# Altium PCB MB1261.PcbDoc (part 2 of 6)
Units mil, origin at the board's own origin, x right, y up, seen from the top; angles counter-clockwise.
Board outline 5119.1 x 2638.79 mil, 6 copper layers (TOP, L2_GND, L3_SIG, L4_VCC, L5_GND, BOTTOM), stack 61 mil thick; 336 components, 316 nets, 1358 pads, 871 vias.
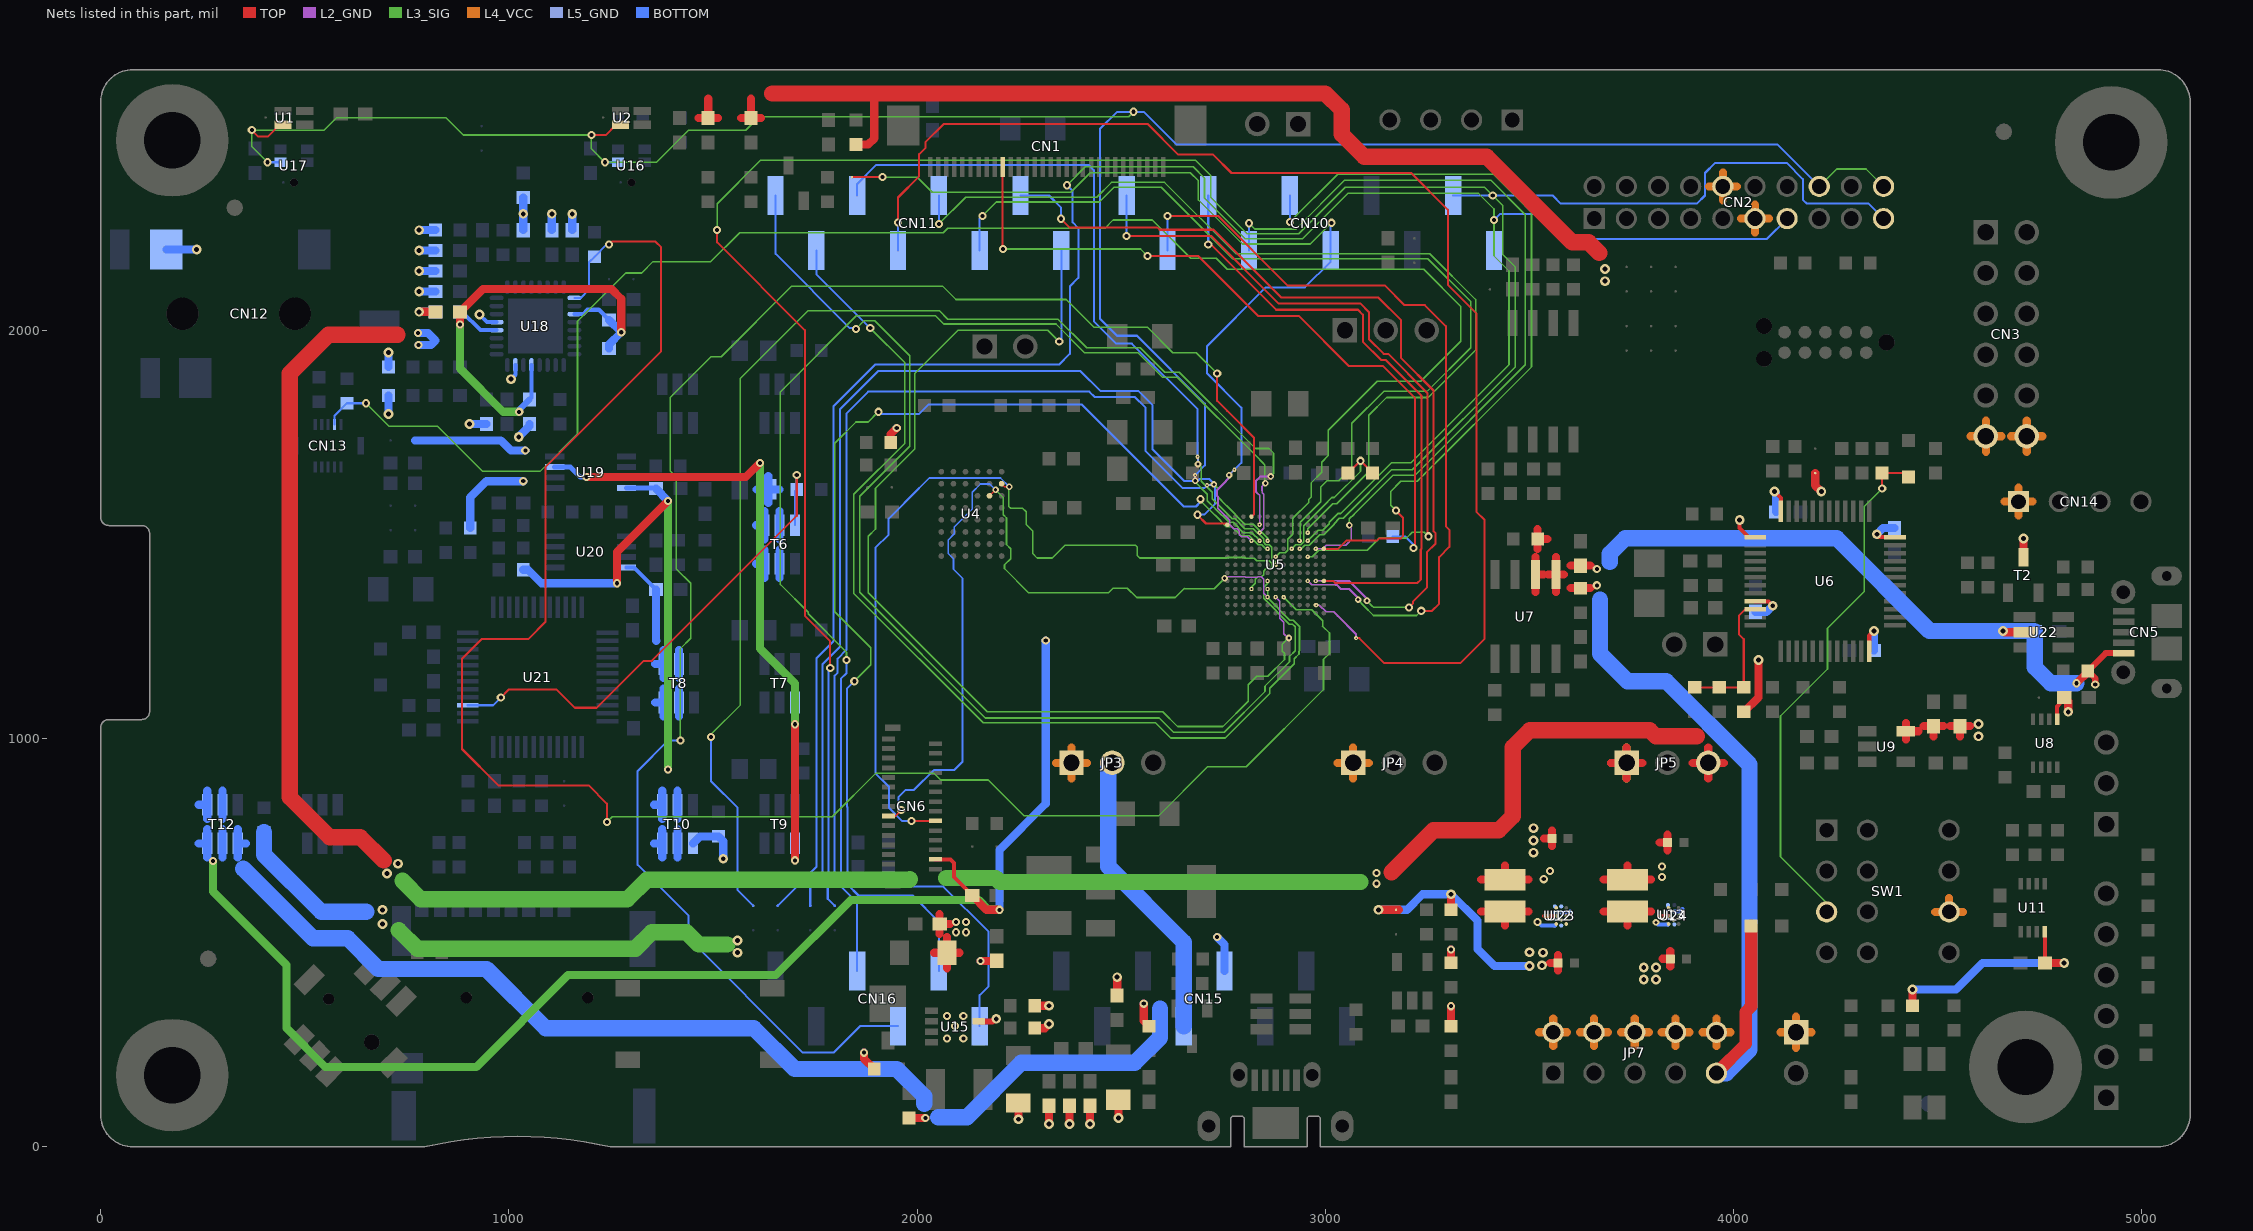
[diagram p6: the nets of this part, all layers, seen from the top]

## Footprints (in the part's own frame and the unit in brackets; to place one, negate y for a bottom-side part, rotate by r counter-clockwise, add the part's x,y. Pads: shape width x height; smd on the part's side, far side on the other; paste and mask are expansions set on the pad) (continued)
SOT23-5 [mil] "SOT23-5"
  rect 25x45 smd: 1(-37.4,-47.24) 2(0,-47.24) 3(37.4,-47.24) 4(37.4,47.24) 5(-37.4,47.24)
  silkscreen extent -65,-101 65,35, body extent -57,-70 57,70, height 150
SOT23-6L [mil] "SOT23-6L"
  rect 25x53 smd: 1(-37.4,-47.24) 2(0,-47.24) 3(37.4,-47.24) 4(37.4,47.24) 5(0,47.24) 6(-37.4,47.24)
  silkscreen extent -75,-95 65,85, body extent -57,-75 57,75, height 150
SOT-23 [mil] "SOT-23"
  rect 25x45 smd: 1(-37.4,-43.31) 2(37.4,-43.31) 3(0,43.31)
  silkscreen extent -60,-35 60,35, body extent -60,-70 60,70, height 150
SOT-223 [mil] "SOT-223"
  rect 71x40 smd: 1(124.02,-90.55) 2(124.02,0) 3(124.02,90.55)
  rect 71x130 smd: 4(-124.02,0)
  silkscreen extent -75,-147 192,130, body extent -160,-128 160,128, height 150
SQT-110-01-F-D-RA [mil] "SQT-110-01-F-D-RA"
  rect 52x52 hole 36: 1(359.27,175)
  round 52 hole 36: 2(280.53,175) 3(201.79,175) 4(123.05,175) 5(44.31,175) 6(-34.43,175) 7(-113.17,175) 8(-191.91,175) 9(-270.65,175) 10(-349.39,175) 11(359.27,96.26) 12(280.53,96.26) 13(201.79,96.26) 14(123.05,96.26) 15(44.31,96.26) 16(-34.43,96.26) 17(-113.17,96.26) 18(-191.91,96.26) 19(-270.65,96.26) 20(-349.39,96.26)
  silkscreen extent -395,-204 405,186, body extent -402,-205 402,205, height 150
SSW-106-02-F-D-RA [mil] "SSW-106-02-F-D-RA"
  rect 60x60 / inner round 60 / far side rect 60x60 hole 40: 1(250,229.5)
  round 60 hole 40: 2(150,229.5) 3(50,229.5) 4(-50,229.5) 5(-150,229.5) 6(-250,229.5) 7(250,129.5) 8(150,129.5) 9(50,129.5) 10(-50,129.5) 11(-150,129.5) 12(-250,129.5)
  silkscreen extent -310,-266 320,243, body extent -310,-264 310,264, height 150
SSW-106-22-X-S-VS [mil] "SSW-106-22-X-S-VS"
  rect 40x95 smd: 1(250,67.5) 2(150,-67.5) 3(50,67.5) 4(-50,-67.5) 5(-150,67.5) 6(-250,-67.5)
  silkscreen extent -310,-47 310,149, body extent -310,-120 310,120, height 150
SSW-108-22-X-S-VS [mil] "SSW-108-22-X-S-VS"
  rect 40x95 smd: 1(350,67.5) 2(250,-67.5) 3(150,67.5) 4(50,-67.5) 5(-50,67.5) 6(-150,-67.5) 7(-250,67.5) 8(-350,-67.5)
  silkscreen extent -410,-47 414,152, body extent -410,-120 410,120, height 150
SSW-110-22-X-S-VS [mil] "SSW-110-22-X-S-VS"
  rect 40x95 smd: 1(450,67.5) 2(350,-67.5) 3(250,67.5) 4(150,-67.5) 5(50,67.5) 6(-50,-67.5) 7(-150,67.5) 8(-250,-67.5) 9(-350,67.5) 10(-450,-67.5)
  silkscreen extent -510,-47 510,153, body extent -510,-120 510,120, height 150
SW1_11R7X9R7-12R2X9R65-HDR_CPT [mil] "SW1_11R7X9R7-12R2X9R65-HDR_CPT"
  rect 52x52 hole 36: 1(-150,-150)
  round 52 hole 36: 2(-50,-150) 3(50,-150) 4(150,-150) 5(150,150) 6(50,150) 7(-50,150) 8(-150,150) " "(-150,-50) " "(-50,-50) " "(50,-50) " "(150,-50)
  TOP region: 24.02,-51.97 75.98,-51.97 75.98,151.97 24.02,151.97 24.02,-51.97
  TOP region: -75.98,-51.97 -24.02,-51.97 -24.02,151.97 -75.98,151.97 -75.98,-51.97
  TOP region: -175.98,-51.97 -124.02,-51.97 -124.02,151.97 -175.98,151.97 -175.98,-51.97
  TOP region: 124.02,-51.97 175.98,-51.97 175.98,151.97 124.02,151.97 124.02,-51.97
  silkscreen extent -240,-231 240,191, body extent -240,-191 240,191, height 150
TAN-A [mil] "TAN-A"
  rect 50x60 smd: 1(55,0) 2(-55,0)
  silkscreen extent -95,-45 105,45
TAN-B [mil] "TAN-B"
  rect 59x110 smd: 1(-67.5,0) 2(67.5,0)
  silkscreen extent -130,-65 110,65, body extent -100,-55 100,55, height 150
TC2050-IDC-NL [mil] "TC2050-IDC-NL"
  round 31 smd paste-50: 1(-100.2,-25) 2(-50.2,-25) 3(-0.2,-25) 4(49.8,-25) 5(99.8,-25) 6(99.8,25) 7(49.8,25) 8(-0.2,25) 9(-50.2,25) 10(-100.2,25)
  round 39 hole 39 unplated: " "(-150.2,0) " "(149.8,-39.96) " "(149.8,39.96)
  TOP pour cut-out: -100.2,18.9 -100.2,-14.9 99.8,-14.9 99.8,18.9 -100.2,18.9
  Multi-Layer pour cut-out: -150.2,-35.43 -163.76,-32.73 -175.25,-25.05 -182.93,-13.56 -185.63,0 -185.63,0 -182.93,13.56 -175.25,25.05 -163.76,32.73 -150.2,35.43 -150.2,35.43 -136.64,32.73 -125.15,25.05 -117.47,13.56 -114.77,0 -114.77,0 -117.47,-13.56 -125.15,-25.05 -136.64,-32.73 -150.2,-35.43
  Multi-Layer pour cut-out: 149.8,4.53 136.24,7.23 124.75,14.91 117.07,26.4 114.37,39.96 114.37,39.96 117.07,53.52 124.75,65.01 136.24,72.69 149.8,75.39 149.8,75.39 163.36,72.69 174.85,65.01 182.53,53.52 185.23,39.96 185.23,39.96 182.53,26.4 174.85,14.91 163.36,7.23 149.8,4.53
  Multi-Layer pour cut-out: 149.8,-75.39 136.24,-72.69 124.75,-65.01 117.07,-53.52 114.37,-39.96 114.37,-39.96 117.07,-26.4 124.75,-14.91 136.24,-7.23 149.8,-4.53 149.8,-4.53 163.36,-7.23 174.85,-14.91 182.53,-26.4 185.23,-39.96 185.23,-39.96 182.53,-53.52 174.85,-65.01 163.36,-72.69 149.8,-75.39
  silkscreen extent -245,-132 245,133, body extent -245,-133 245,133, height 150
USOP8_0R5_2X3R1 [mil] "USOP8_0R5_2X3R1"
  rect 11x28 smd mask+2: 1(-29.53,-59.06) 2(-9.84,-59.06) 3(9.84,-59.06) 4(29.53,-59.06) 5(29.53,59.06) 6(9.84,59.06) 7(-9.84,59.06) 8(-29.53,59.06)
  silkscreen extent -47,-106 40,30, body extent -40,-75 40,75, height 150
XTAL_2SM_3R2X1R5 [mil] "XTAL_2SM_3R2X1R5"
  rect 51x63 smd: 1(-45.78,-1) 2(44.78,-1)
  silkscreen extent -86,-46 84,44, body extent -72,-31 72,31, height 150
XTAL_2SM_3R2X2R5 [mil] "XTAL_2SM_3R2X2R5"
  rect 67x75 smd: 1(-49.21,0) 2(49.21,0)
  silkscreen extent -63,-49 63,49, body extent -85,-50 85,50, height 150

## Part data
B1: library part "SW PUSHBUTTON", "SE Push Button TD-0341 [RESET/Black]", Manuf_1=Chau-hua, Manuf_2=wealthmetal, Manuf_Part_1=CTSM-644N-V-T/R
B2: library part MT-008A, "Joystick", Manuf_1=XIEJIA
C1 C2 C4 C5 C7 C10 C12 C14 C15 C16 C17 C18 C21 C22 C24 C25 C26 C27 C28 C29 C30 C31 C33 C34 C44 C46 C51 C58 C59 C60 C66 C71 C72 C73 C80 C81 C82 C83 C85 C86 C87 C88 C89 C90 C92 C93 C94 C95 C96 C97 C98 C101 C102 C103 C104 C105: library part Cap, "Capacitor,100nF,10%,16V,X7R,0603,YAGEO", Manuf_1=YAGEO
C3 C62 C63 C99: library part Cap, "Capacitor,100nF,10%,16V,X7R,0603,YAGEO", Manuf_1=YAGEO, Manuf_Part_1=CC0603KRX7R7BB104
C6: library part "Cap Pol1", "TAN Capacitor,4.7uF,10%,16V,A Type,AVX", Manuf_1=AVX
C8 C13 C91 C100: library part "Cap Pol1", "Tan Capacitor,1uF,10%,16V,Tan-A,TAJA105K016R", Manuf_1=AVX
C9 C11: library part Cap, "Capacitor,5.6pF,0.25P,50V,NPO,0603", Manuf_1=YAGEO
C19 C32 C35 C67 C69 C70 C74 C77 C78 C79 C84: library part Cap, "Capacitor,1uF,0603,16V,10%,X5R,YAGEO", Manuf_1=YAGEO
C20 C23: library part Cap, "Capacitor,10pF,5%,50V,NPO,0603,YAGEO", Manuf_1=YAGEO
C36 C47 C57: library part MCD-00017, "Capacitor, MLCC, 10nF, 50V, X7R, +/-10%, 0603, T=0.8mm", Manufacturer=YAGEO, Package=0603
C37 C55 C61: library part "Cap Pol1", "TAN Capacitor,10uF,10%,16V,A Type,AVX", Manuf_1=AVX
C40 C41 C42 C43: library part MCD-01532, "Capacitor, MLCC, 10uF, 10V, X5R, +/-20%, 0402, T=0.5mm", Manufacturer=MURATA, Manufacturer_Part_Number=GRM155R61A106ME11, Package=0402
C45: library part "Cap Pol1", "Tan Capacitor,10uF,10%,25V,Tan-B,TAJB106K025RNJ", Manuf_1=AVX
C48: library part CAP, "Capacitor,4.7uF,50V,X7R,10%,1206", Manuf_1=YAGEO
C54: library part Cap, "Capacitor,4.7uF,16V, X5R,10%,0603", Manuf_1=YAGEO
C56: library part "Cap Pol1", "Capacitor,4.7uF,±10%,X7R,10V,1206,C1206X475K8NAC", Manuf_1=Kemet
C64 C65: library part Cap, "Capacitor,150pF,0603,50V,5%,NPO", Manuf_1=YAGEO
C68: library part Cap, "Capacitor,10uF,10%,10V,X5R,0603,C1608X5R1A106K080AC", Manuf_1=TDK, Manuf_Part_1=C1608X5R1A106KT000E
C75 C76: library part Cap, "Capacitor,22nF,10%,25V,X7R,0603", Manuf_1=YAGEO
CN1: "TOWNES -  Connector FFC/FPC ZIF 0.5mm 30 pins, Lower Contacts", Manuf_1=TOWNES, Manuf_Part_2=TFP-A330ZH-BT1-ECX
CN2: library part "Header 10X2A", "Header, 10-Pin, Dual row", Manuf_1=ATOM, Manuf_Part_1=FH200210C-12000
CN3: library part "Header 6X2A", "Header, 6-Pin, Dual row", Manuf_1=ATOM, Manuf_Part_1=FH254206C-1600
CN4: "Footprint for TC2050-IDC-430 plug of nails (TM) cable for MP430", Manuf_1=None
CN5 CN8: Manuf_1=MOLEX
CN6: library part FH26-29S-0.3SHW, "29pins FPC connector", Manuf_1=Hirose
CN7: library part "Header 6", "Header, 6-Pin", Manuf_1=lyconn
CN9 CN14: library part "Header 4", "Header, 4-Pin"
CN10: library part MCD-00301, "Socket, 10x1, 2.54mm, VR, SMD, T=9.78mm", Manufacturer=SAMTEC, Manufacturer_Part_Number=SSW-110-22-L-S-VS
CN11 CN15: library part "Header 8X1_Female", "Header, 8-Pin, Single row,female", Manuf_1=SAMTEC
CN12: Manuf_1=QIAOD
CN13: library part "Header 5X2A", "Header, 5-Pin, Dual row", Manuf_1=Hirose
CN16: library part MCD-00299, "Socket, 6x1, 2.54mm, VR, SMD, T=9.78mm", Manufacturer=SAMTEC, Manufacturer_Part_Number=SSW-106-22-L-S-VS
CN17: library part SMS016AFA5E, Manuf_1=Yamaichi
D1 D3 D6 U22: Manuf_1=STM
D2 D4: library part BAT60JFILM, "BAT60JFILM", Manuf_1=STM
D5: "4-line ESD protection", Manuf_1=STM, Manuf_Part_1=ESDA5V3L
JP1: library part JP2, "2 PIN Jumper", Manuf_1=lyconn, Manuf_Part_1=313102S111116
JP2: library part Jumper3, "Jumper 3 pins", Manuf_1=lyconn, Manuf_Part_1=313103S111116
JP3 JP5 JP6: library part Jumper3, Manuf_1=lyconn, Manuf_Part_1=313103S111116
JP4: Manuf_1=lyconn, Manuf_Part_1=313103S111116
JP7: library part "Header 5X2M", "Pin Header male,2.54mm,2*5,L=11.6,180,1U,DIP", Manuf_1=Lyconn
JP8 JP9 JP10: library part JP2, Manuf_1=lyconn, Manuf_Part_1=313102S111116
L1 L4 L5 L6 L8: library part MCD-00047, "Ferrite bead, 600R @1 00MHz, +/-25%, 350mA, 0R5, 0603, T=0.8mm", Manufacturer=TAI-TECH, Package=0603
L2 L3: library part Inductor, "Inductor", Manuf_1=TDK, Manuf_Part_1=VLS252010HBX-2R2M-1
L7: library part Inductor, "IND,4.7uH,1A,1210,LQH32PN4R7NN0L", Manuf_1=Murata
LD1: library part MCD-02785, "LED, Orange, 2V2, 5mA, 0603", Manufacturer=EVERLIGHT, Manufacturer_Part_Number=19-217/S2C-AM2N2VY/6T, Package=0603
LD2 LD3 LD6 LD8: library part MCD-02901, "LED, Green, 2V, 20mA, 0603", Manufacturer=EVERLIGHT, Manufacturer_Part_Number=19-217/G7C-AN1P2/6T, Package=0603
LD4 LD7: library part MCD-02787, "LED, Red, 1V7 To 2V2, 5mA, 0603", Manufacturer=EVERLIGHT, Manufacturer_Part_Number=19-217/R6C-AL1M2VY/6T, Package=0603
LD5: library part MCD-02402, "LED Bicolor, Red/Yellow-Green , 2V, 20mA, 4-PLCC", Manufacturer=EVERLIGHT, Manufacturer_Part_Number=67-22SURSYGC/S530-A2/TR8, Package=4-PLCC
R1: library part res1, "Resistor,680R,0603,1%,YAGEO", Manuf_1=YAGEO
R2 R112: library part res1, "Resistor,510R,0603,1%,YAGEO", Manuf_1=YAGEO
R4 R5 R16 R25 R35 R56 R59 R60 R63 R66 R69 R71 R102: library part res1, "Resistor, 100 ,0603,1%,YAGEO", Manuf_1=YAGEO
R6 R7 R8 R26 R28 R29 R100: library part res1, "Resistor, 22 ,0603,1%,YAGEO", Manuf_1=YAGEO
R12 R18 R130: library part res1, "Resistor, 0 ,0603,1%,YAGEO", Manuf_1=YAGEO, Manuf_Part_1=RC0603JR-070RL
R13 R14 R15 R17 R20 R33 R48 R52 R53 R54 R73 R76 R81 R84 R94 R106 R109 R110 R115 R116 R117: library part res1, "Resistor,100K,0603,1%,YAGEO", Manuf_1=YAGEO
R21 R31 R41 R77 R89 R99 R104: library part res1, "Resistor,100K,0603,1%,YAGEO", Manuf_1=YAGEO, Manuf_Part_1=RC0603FR-07100KL
R22 R45 R49: library part res1, "Resistor,4.7K,0603,1%,YAGEO", Manuf_1=YAGEO
R23: library part res1, "Resistor,2.7K,0603,1%,YAGEO", Manuf_1=YAGEO
R24: library part Res_0_5%_0402, "Resistor,0,0603,5%,YAGEO", Manuf_1=YAGEO, Manuf_Part_1=RC0603JR-070RL
R27 R30 R32 R44 R78 R83 R91 R113: library part res1, "Resistor,10K,0603,1%,YAGEO", Manuf_1=YAGEO
R34: library part res1, "Resistor,36K,0603,1%,YAGEO", Manuf_1=YAGEO
R36 R68: library part res1, "Resistor", Manuf_1=YAGEO, Manuf_Part_1=RC0603FR-07820RL
R37 R42 R43: library part res1, "Resistor,1.5K,0603,1%,YAGEO", Manuf_1=YAGEO
R46 R47 R51 R55 R57 R70 R80 R93 R105 R114 R129: library part res1, "Resistor, 0 ,0603,1%,YAGEO", Manuf_1=YAGEO
R50 R82: library part res1, "Resistor,2.2K,0603,1%,YAGEO", Manuf_1=YAGEO
R58 R62 R64: library part res1, "Resistor, 47K,0603,1%,YAGEO", Manuf_1=YAGEO
R65: library part res1, "Resistor, 10K,0603,1%,YAGEO", Manuf_1=YAGEO
R67: library part res1, "Resistor,10R,0603,1%,YAGEO", Manuf_1=YAGEO
R72: library part res1, "Resistor,1K,0603,1%", Manuf_1=YAGEO, Manuf_Part_1=RC0603FR-071KL
R74: library part res1, "Resistor, 330R , 0603,1%,YAGEO", Manuf_1=YAGEO
R75: library part res1, "Resistor, 620R , 0603,1%,YAGEO", Manuf_1=YAGEO
R79: library part res1, "Resistor,10K,0603,1%,YAGEO", Manuf_1=YAGEO, Manuf_Part_1=RC0603FR-0710KL
R85: library part Res_1_1%_0805, "Resistor,1,0805,1%,YAGEO", Manuf_1=YAGEO, Manuf_Part_1=RC0805FR-071RL
R86 R90: library part res1, "Resistor,50R,0603,1%,YAGEO", Manuf_1=YAGEO
R87 R88: library part res1, "Resistor,1.5K,0603,1%,YAGEO", Manuf_1=YAGEO, Manuf_Part_1=RC0603FR-071K5L
R92 R96: library part res1, "Resistor,6.04K,0603,1%,YAGEO", Manuf_1=YAGEO
R95: library part Res_10K_1%_0805, "Resistor,10K,0805,1%,YAGEO", Manuf_1=YAGEO, Manuf_Part_1=RC0805FR-0710KL
R97 R103: library part res1, "Resistor,300K,0603,1%,YAGEO", Manuf_1=YAGEO
R98: library part res1, "Resistor,11K,0603,1%,YAGEO", Manuf_1=YAGEO
R101: library part res1, "Resistor,357K,0603,1%,YAGEO", Manuf_1=YAGEO
R107: library part Res_24_1%_0805, "Resistor,24,0805,1%,YAGEO", Manuf_1=YAGEO, Manuf_Part_1=RC0805FR-0724RL
R111: library part Res_620_1%_0805, "Resistor,620,0805,1%,YAGEO", Manuf_1=YAGEO, Manuf_Part_1=RC0805FR-07620RL
R118 R119 R120 R121 R122: library part res1, "Resistor,47K,0603,1%,YAGEO", Manuf_1=YAGEO, Manuf_Part_1=RC0603FR-0747KL
R123: library part res1, "Resistor, 510R , 0603,1%,YAGEO", Manuf_1=YAGEO
R124: library part res1, "Resistor, 1M , 0603"
SB1 SB3 SB6 SB7 SB8 SB12 SB13 SB14 SB16 SB17 SB18 SB19 SB20 SB21 SB24 SB26 SB28: library part SB_ON, Manuf_1=YAGEO, Manuf_Part_1=RC0603JR-070RL
SB2 SB4 SB5 SB9 SB11 SB15 SB22 SB25 SB27: library part SB_OFF
SW1: "Gold Plated Contacts,4PST,1x4 Switch", Manuf_1="Grayhill Inc"
T1: library part 2N7000, Manuf_1=NXP
T2 T3: library part NPN, "NPN Bipolar Transistor", Manuf_Part_1=MMBT9013
T4 T5 T6 T7 T8 T9 T10 T11 T12: library part MCD-01926, "20 V, P-channel Trench MOSFET", Alternate_Manufacturer=N/A, Manufacturer=NEXPERIA, Package=TSOP6
U1 U2: library part MCD-01715, "MEMS audio sensor omnidirectional digital microphone for industrial applications", Manufacturer=STMICROELECTRONICS, Manufacturer_HQ_COO=EU, Package=HCLGA-4LD
U3: "Ultra Low Power 64M-BIT CMOS MXSMIO FLASH MEMORY", Manuf_1=MXIC
U4: "8M Bit static RAMs organized as 512K words by  16 bits.", Manuf_1=ISSI
U5: library part STM32L496G, Manuf_1=STM
U6: library part STM32F10x(48pin), "IC,STM32F103CBT6,LQFP-48", Manuf_1=STM
U7: Manuf_1=ST
U8 U11: Manuf_1=TI
U9: "Ultra low drop-low noise BiCMOS voltage, regulators low ESR capacitors compatible", Manuf_1=STM, Manuf_Part_2=LDK120DM33R
U10: library part LD1117S18TR, "Adjustable and fixed low drop positive voltage regulator", Manuf_1=STM
U12 U13: "High Efficiency Buck Converter", Manuf_1=TI
U14: "Enhanced single channel power switches", Manuf_1=ST
U15: library part STLD40DPMR, Manuf_1=ST
U16 U17: library part MCD-02122, "MEMS, Audio sensor Multi performance mode digital microphone", Manufacturer=STMICROELECTRONICS, Manufacturer_HQ_COO=EU, Manufacturer_Part_Number=MP23DB01HPTR, Package=RHLGA-5
U18: "Low-Power, Stereo Codec with Headphone Amp", Manuf_1=Cirrus
U19 U20: "Very high accuracy (5 礦) zero drift 5 V dual OpAmp", Manuf_1=STM
U21: library part MFX, "Multifunction expander", Manuf_1=STM
U23 U24: "400mA NanoQuiescent Step Down converter", Manuf_1=STM
X1: library part CRYSTAL_32K, "32.768kHz Crystal", Manuf_1=NDK, Manuf_Part_1=NX3215SA-32.768KHZ-EXS00A-MU00525
X2: library part XTAL_8M_NX3225GD, "Crystal 8Mhz, 8pF, -+50PPM, SMD", Manuf_1=NDK, Manuf_Part_1="NX3225GD 8MHz EXS00A-CG04874", Manuf_Part_2=NX3225GD-8.000M-STD-CRA-3
Z1: library part "D Schottky", "Schottky Diode", Manuf_1=STM

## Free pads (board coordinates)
  round 40 smd far side mask+40: 1(263.1,460) 1(4662.1,2486) ""(4478.1,105)
  round 40 smd mask+40: ""(263.1,460) ""(328.1,2300) ""(4662.1,2486)

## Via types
v1: diameter 20, hole 10, TOP to BOTTOM, tented both sides, 317 vias
v2: diameter 24, hole 12, TOP to BOTTOM, tented both sides, 289 vias
v3: diameter 10, hole 4, TOP to L2_GND, tented both sides, 76 vias
v4: diameter 10, hole 4, TOP to L3_SIG, tented both sides, 63 vias
v5: diameter 16, hole 8, L2_GND to L5_GND, tented both sides, 52 vias
v6: diameter 16, hole 8, TOP to BOTTOM, tented both sides, 43 vias
v7: diameter 10, hole 4, L5_GND to BOTTOM, tented both sides, 31 vias

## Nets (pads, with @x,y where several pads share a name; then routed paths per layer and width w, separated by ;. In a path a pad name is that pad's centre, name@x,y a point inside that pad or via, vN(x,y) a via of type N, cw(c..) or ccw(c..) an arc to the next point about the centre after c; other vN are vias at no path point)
1V8_CODEC: C5.1 C72.1 C73.1 C74.1 C77.1 SB19.2 U18.5 U18.12 U18.27 | length 1337.8
  TOP w20: v1(880,2014) C5.1@880,2045 936,2101 1251,2101 1275,2077 v1(1275,1995)
  L3_SIG w20: v1(880,2014) 880,1906 986,1800 v1(1025,1800)
  BOTTOM w10: C72.1@880,2045 885,2045 929.84,2000.16 U18.12@969.72,2000.16 ; C77.1@1050,1830 1055.16,1835.16 U18.5@1055.16,1914.72 ; U18.27@1160.28,2039.53 1182.4,2039.53 1192.87,2050 1220,2050 C73.1@1245,2025
  BOTTOM w15: v1(1025,1800) 1025,1805 C77.1@1050,1830
  BOTTOM w20: SB19.2@880,1975 v1(880,2014) C72.1@880,2045 ; C74.1@1245,1955 1245,1965 v1(1275,1995) C73.1@1245,2025
1V8_OUT: C41.1 JP5.3 L3.2 SB19.1 U13.C2 U24.E3 | length 5413.4
  TOP w20: 3681.98,654 L3.2@3740,654 ; 3740,688.52 L3.2@3740,654 ; 3798.02,654 L3.2@3740,654 ; 3819.08,745 C41.1@3838.1,745 ; 3838.1,725.98 C41.1@3838.1,745 ; 3838.1,764.02 C41.1@3838.1,745 ; 3900.08,940 JP5.3@3938.1,940 ; 3938.1,901.98 JP5.3@3938.1,940 ; 3938.1,978.02 JP5.3@3938.1,940 ; 3976.12,940 JP5.3@3938.1,940
  TOP w40: 693,701 636,758 561,758 463,856 463,1894 558,1989 727,1989 ; 3162,672 3265,775 3425,775 3459,809 3459,978 3501,1020 3795,1020 3810,1005 3910,1005
  L3_SIG w40: 739,651 784,606 1290,606 1338,654 1981,654 1982,655 ; 2071,658 2192,658 2202,648 3086,648
  BOTTOM w9: U13.C2@3854.87,575.87 3868.87,575.87 3875,582
  BOTTOM w20: v1(776.99,1992.99) 777,1992.93 802.07,1992.93 SB19.1@820,1975 809,1964 v1(778,1964)
  other v1: 3125,644 3825,660 3125,670 3825,686
  other v2: 701,669 728,693
1V8_SW: L3.1 U13.A1 U24.C3 | length 202.4
  TOP w9: 3820,565 U24.C3@3840.82,565
  TOP w20: 3681.98,576 L3.1@3740,576 ; 3740,541.48 L3.1@3740,576 ; 3798.02,576 L3.1@3740,576
  BOTTOM w10: v6(3810,549) 3814.62,544.38 U13.A1@3839.13,544.38
3V3_LCD: C44.1 CN6.26 R99.2 R130.2 SB20.1 T12.1 T12.2 T12.5 T12.6 | length 4246.6
  TOP w10: CN6.26@2044.44,703.41 2081.59,703.41 2090,695 2090,660 C44.1@2135,615
  TOP w20: R130.2@1935,1725 1935,1745 v1(1950,1760) ; C44.1@2135,615 2170,580 v1(2202,580)
  L3_SIG w20: v1(275,700) 275,625 455,445 455,290 550,195 920,195 1145,420 1653.49,420 1837.49,604 2151,604 2175,580 v1(2202,580)
  BOTTOM w20: 240.18,742.76 T12.6@260.7,742.76 ; 240.18,837.24 T12.1@260.7,837.24 ; 260.7,708.24 T12.6@260.7,742.76 ; 260.7,777.28 T12.6@260.7,742.76 ; 260.7,802.72 T12.1@260.7,837.24 ; 260.7,871.76 T12.1@260.7,837.24 ; 298.1,708.24 T12.5@298.1,742.76 298.1,777.28 ; 298.1,802.72 T12.2@298.1,837.24 298.1,871.76 ; SB20.1@770,1730 980,1730 1005,1705 v1(1040,1705) ; R99.2@905,1515 905,1590 945,1630 v1(1035,1630) ; v1(2202,580) 2202,727 2315,840 v1(2315,1240)
3V3_OUT: C40.1 CN3.6 CN3.12 CN15.4 JP4.1 JP5.1 L2.2 LD1.1 LD2.1 R64.1 R74.1 R75.1 R77.2 R123.1 T12.4 U12.C2 U23.E3 | length 6502.9
  TOP w20: 1464.08,2520 LD1.1@1488.1,2520 ; 1488.1,2567.1 LD1.1@1488.1,2520 ; 1512.12,2520 LD1.1@1488.1,2520 ; 1569.08,2520 LD2.1@1593.1,2520 ; 1593.1,2567.1 LD2.1@1593.1,2520 ; 1617.12,2520 LD2.1@1593.1,2520 ; R123.1@1850,2455 1880,2455 1895,2470 1895,2580 ; R77.2@1980,70 v1(2020,70) ; v1(2555,350) 2555,308.1 R74.1@2568.1,295 ; R75.1@3308.1,295 v1(3308.1,343.9) ; R64.1@3308.1,450 v1(3308.1,483.1) ; 3381.98,654 L2.2@3440,654 ; 3440,688.52 L2.2@3440,654 ; 3498.02,654 L2.2@3440,654 ; 3535.98,755 C40.1@3555,755 ; 3555,735.98 C40.1@3555,755 ; 3555,774.02 C40.1@3555,755 ; 3700.08,940 JP5.1@3738.1,940 ; 3738.1,901.98 JP5.1@3738.1,940 ; 3738.1,978.02 JP5.1@3738.1,940 ; 3776.12,940 JP5.1@3738.1,940
  TOP w40: 1645,2580 1895,2580 3000,2580 3040,2540 3040,2480 3095,2425 3395,2425 3605,2215 3645,2215 3671,2189
  L4_VCC w20: 3030.08,940 JP4.1@3068.1,940 ; 3068.1,901.98 JP4.1@3068.1,940 ; 3068.1,978.02 JP4.1@3068.1,940 ; 3106.12,940 JP4.1@3068.1,940 ; 3700.08,940 JP5.1@3738.1,940 ; 3738.1,901.98 JP5.1@3738.1,940 ; 3738.1,978.02 JP5.1@3738.1,940 ; 4580.08,1740 CN3.6@4618.1,1740 ; 4618.1,1701.98 CN3.6@4618.1,1740 ; 4618.1,1778.02 CN3.6@4618.1,1740 ; 4656.12,1740 CN3.6@4618.1,1740 ; 4680.08,1740 CN3.12@4718.1,1740 ; 4718.1,1701.98 CN3.12@4718.1,1740 ; 4718.1,1778.02 CN3.12@4718.1,1740 ; 4756.12,1740 CN3.12@4718.1,1740
  BOTTOM w9: U12.C2@3577.87,572.87 3595.87,572.87 3600,577
  BOTTOM w20: 335.5,708.24 T12.4@335.5,742.76 ; 335.5,777.28 T12.4@335.5,742.76 ; 356.02,742.76 T12.4@335.5,742.76 ; v1(2735,513) 2753.1,494.9 CN15.4@2753.1,430
  BOTTOM w40: 349,681 520,510 605,510 680,435 945,435 1090,290 1600,290 1700,190 1950,190 2017,123 2017,105 ; 2052,72 2122,72 2255,205 2533.1,205 2595,266.9 2595,338
  other v1: 3535,655 3550,675
  other v2: 3510,720 3510,750 3510,780 3685,2120 3685,2150
3V3_SW: L2.1 U12.A1 U23.C3 | length 227.1
  TOP w9: 3535,565 U23.C3@3565.82,565
  TOP w20: 3381.98,576 L2.1@3440,576 ; 3440,541.48 L2.1@3440,576 ; 3498.02,576 L2.1@3440,576
  BOTTOM w9: v1(3520,550) 3528.62,541.38 U12.A1@3562.13,541.38
5V_STL: D1.1 R24.2 SW1.3 | length 1293.9
  TOP w5: v1(4364.1,1611.9) R24.2@4364.1,1650 4419.81,1650 D1.1@4429.1,1640.71
  L3_SIG w4: SW1.3@4228.1,575 4228.1,596.9 4115,710 4115,1055 4230,1170 4230,1270 4320,1360 4320,1567.8 v1(4364.1,1611.9)
5V_USB_CHARGER: C19.2 C105.1 CN5.1 D3.1 JP7.9 R32.1 R36.2 R44.1 U7.1 U7.2 U22.5 | length 3826.6
  TOP w15: v1(4886,1132) 4886,1147.1 R44.1@4868.1,1165 4911.92,1208.82 CN5.1@4955.7,1208.82
  TOP w20: 3515,1358.38 U7.2@3515,1401.4 ; 3515,1444.42 U7.2@3515,1401.4 ; 3520,1464.08 R32.1@3520,1488.1 ; 3520,1512.12 R32.1@3520,1488.1 ; 3534.02,1401.4 U7.2@3515,1401.4 ; 3543.52,1488.1 R32.1@3520,1488.1 ; 3545.98,1401.4 U7.1@3565,1401.4 ; 3565,1358.38 U7.1@3565,1401.4 ; 3565,1444.42 U7.1@3565,1401.4 ; 3584.02,1401.4 U7.1@3565,1401.4 ; 3600.98,1368.1 R36.2@3625,1368.1 3649.02,1368.1 ; 3600.98,1423.1 C19.2@3625,1423.1 3649.02,1423.1 ; v2(4660,1263) 4663,1260 U22.5@4712.76,1260 ; v1(4840,1135) 4868.1,1163.1 R44.1@4868.1,1165
  TOP w30: JP7.9@3958.1,180 4030,251.9 4030,329.9 4043.1,343 D3.1@4043.1,540.71
  BOTTOM w40: 3673,1340 3673,1207 3740,1140 3835,1140 4039,936 4039,237 3982,180 JP7.9@3958.1,180 ; 3697,1432 3697,1452 3735,1490 4253,1490 4480,1263 v2(4660,1263) 4737,1263 C105.1@4738,1262 4738,1174 4777,1135 v1(4840,1135)
  other v1: 3665,1375 3665,1415
+3V3_ST_LINK: C30.2 C31.1 C32.1 C51.2 C86.1 C87.1 C92.1 C96.1 CN14.1 R41.1 R70.1 SB11.1 T2.3 U6.1 U6.9 U6.24 U6.36 U6.48 U8.1 U9.5 U11.8 | length 1723.1
  TOP w10: v2(4015,1535) 4015,1515 4036.73,1493.27 U6.1@4052.84,1493.27 ; U6.9@4052.84,1335.79 4085.21,1335.79 v2(4096,1325) ; v2(4100,1605) 4115.83,1589.17 U6.48@4115.83,1556.26 ; U6.24@4332.37,1213.74 4332.37,1251.37 v2(4344.1,1263.1) ; v2(4351,1500) 4357.73,1493.27 U6.36@4395.36,1493.27 ; U11.8@4762.63,525.94 4762.63,450.47 C51.2@4763.1,450 ; U8.1@4792.63,1047.06 4792.63,1077.63 C30.2@4810,1100
  TOP w20: R41.1@4025,1065 4061,1100 v2(4061,1192) ; SB11.1@4200,1650 4200,1620 v2(4215,1605) ; 4422.24,996.88 U9.5@4422.24,1017.4 ; 4422.24,1037.92 U9.5@4422.24,1017.4 ; R70.1@4438.1,345 v2(4438.1,385) ; 4452.76,1017.4 U9.5@4422.24,1017.4 ; 4465.98,1030 C31.1@4490,1030 ; 4490,1004.48 C31.1@4490,1030 ; 4514.02,1030 C31.1@4490,1030 ; 4530.98,1030 C32.1@4555,1030 ; 4555,1004.48 C32.1@4555,1030 ; 4579.02,1030 C32.1@4555,1030 ; T2.3@4710,1443.31 v2(4710,1490) ; C51.2@4763.1,450 v2(4810,450) ; C30.2@4810,1100 4820,1090 v2(4820,1065)
  L4_VCC w20: 4664.08,1580 CN14.1@4698.1,1580 ; 4698.1,1545.98 CN14.1@4698.1,1580 ; 4698.1,1614.02 CN14.1@4698.1,1580 ; 4732.12,1580 CN14.1@4698.1,1580
  BOTTOM w20: C92.1@4054.1,1310 4081,1310 v2(4096,1325) ; v2(4100,1605) 4104.1,1600.9 C86.1@4104.1,1555 ; C96.1@4344.1,1215 v2(4344.1,1263.1) ; v2(4351,1500) 4366,1515 C87.1@4394.1,1515 ; v2(4438.1,385) 4545,385 4610,450 v2(4810,450)
  other v2: 4600,1005 4600,1035
+5V: C42.1 C43.1 CN2.6 CN2.15 JP3.1 JP7.2 JP7.4 JP7.6 JP7.8 JP7.10 JP8.1 L5.1 R58.1 R115.1 R116.2 SB16.1 SW1.6 T10.4 U12.A2 U12.B1 U12.C1 U12.D1 U12.D2 U13.A2 U13.B1 U13.D1 U23.A1 U23.A3 U23.B2 U23.C1 U24.A3 U24.B2 | length 3451.1
  TOP w20: L5.1@2490,370 v2(2490,415) ; v2(3130,580) SB16.1@3173.1,580 3180,580 ; R58.1@3308.1,580 v2(3308.1,618.1) ; 3550.98,450 C42.1@3570,450 ; 3570,430.98 C42.1@3570,450 ; 3570,469.02 C42.1@3570,450 ; 3825.98,460 C43.1@3845,460 ; 3845,440.98 C43.1@3845,460 ; 3845,479.02 C43.1@3845,460
  L3_SIG w40: 730,530 775,485 1310,485 1350,525 1435,525 1465,495 1535,495
  L4_VCC w20: 2340.08,940 JP3.1@2378.1,940 ; 2378.1,901.98 JP3.1@2378.1,940 ; 2378.1,978.02 JP3.1@2378.1,940 ; 2416.12,940 JP3.1@2378.1,940 ; 3524.08,280 JP7.2@3558.1,280 ; 3558.1,245.98 JP7.2@3558.1,280 ; 3558.1,314.02 JP7.2@3558.1,280 ; 3592.12,280 JP7.2@3558.1,280 ; 3624.08,280 JP7.4@3658.1,280 ; 3658.1,245.98 JP7.4@3658.1,280 ; 3658.1,314.02 JP7.4@3658.1,280 ; 3692.12,280 JP7.4@3658.1,280 ; 3724.08,280 JP7.6@3758.1,280 ; 3758.1,245.98 JP7.6@3758.1,280 ; 3758.1,314.02 JP7.6@3758.1,280 ; 3792.12,280 JP7.6@3758.1,280 ; 3824.08,280 JP7.8@3858.1,280 ; 3858.1,245.98 JP7.8@3858.1,280 ; 3858.1,314.02 JP7.8@3858.1,280 ; 3892.12,280 JP7.8@3858.1,280 ; 3924.08,280 JP7.10@3958.1,280 ; 3939.71,2352.16 CN2.15@3973.73,2352.16 ; 3958.1,245.98 JP7.10@3958.1,280 ; 3958.1,314.02 JP7.10@3958.1,280 ; 3973.73,2318.14 CN2.15@3973.73,2352.16 ; 3973.73,2386.18 CN2.15@3973.73,2352.16 ; 3992.12,280 JP7.10@3958.1,280 ; 4007.75,2352.16 CN2.15@3973.73,2352.16 ; 4018.45,2273.42 CN2.6@4052.47,2273.42 ; 4052.47,2239.4 CN2.6@4052.47,2273.42 ; 4052.47,2307.44 CN2.6@4052.47,2273.42 ; 4086.49,2273.42 CN2.6@4052.47,2273.42 ; 4115.08,280 JP8.1@4153.1,280 ; 4153.1,241.98 JP8.1@4153.1,280 ; 4153.1,318.02 JP8.1@4153.1,280 ; 4191.12,280 JP8.1@4153.1,280 ; 4494.08,575 SW1.6@4528.1,575 ; 4528.1,609.02 SW1.6@4528.1,575 ; 4562.12,575 SW1.6@4528.1,575
  BOTTOM w20: T10.4@1450.5,742.76 1467.74,760 R116.2@1513.1,760 1525,748.1 v2(1525,705) ; v2(3130,580) 3200,580 3238.1,618.1 v2(3308.1,618.1) 3372.5,553.7 3372.5,483.5 3414,442 v2(3500,442)
  BOTTOM w40: R115.1@400,770 400,715 540,575 650,575
  other v2: 3780,409 3810,409 3780,439 3810,439 3531,444 1560,475 3533,475 3500,476 1560,505 690,545 690,580
AGND: C5.2 C64.2 C65.2 C66.1 C68.1 C69.1 C70.1 C72.2 C77.2 C79.1 CN12.3 R80.2 R81.2 R86.2 R90.2 U18.7 U18.13 | length 726.8
  TOP w20: v2(780,2045) C5.2@820,2045
  BOTTOM w9: v2(928.1,2038.1) 946.36,2019.84 U18.13@969.72,2019.84
  BOTTOM w10: v2(1005,1880) 1015.79,1890.79 U18.7@1015.79,1914.72
  BOTTOM w20: CN12.3@160.63,2197.48 v2(235,2197.48) ; v2(705,1795) R90.2@705,1840 ; R86.2@705,1910 v2(705,1945) ; v2(780,2045) C72.2@820,2045 ; v2(780,2095) C70.1@820,2095 ; v2(780,2145) C69.1@820,2145 ; v2(780,2195) C68.1@820,2195 ; v2(780,2245) R81.2@820,2245 ; v2(903,1770) C79.1@945,1770 ; v2(1024,1738.65) 1025,1739.65 1025,1740 1050,1765 C77.2@1050,1770 ; C66.1@1035,2245 v2(1035,2285) R80.2@1035,2325 ; C65.2@1105,2245 v2(1105,2285) ; C64.2@1155,2245 v2(1155,2284.9)
AIN_1: R41.2 R45.1 R49.1 U6.10 | length 346.5
  TOP w5: R49.1@3905,1125 R45.1@3965,1125 R41.2@4025,1125 4025,1243 4013,1255 4013,1300 4029.1,1316.1 U6.10@4052.84,1316.1
AMP_5V: C83.2 R105.2 T10.1 T10.2 T10.5 T10.6 U19.8 | length 1587.6
  TOP w20: v1(1265,1380) 1265,1456.9 v1(1390,1581.9)
  L3_SIG w20: v1(1390,924) v1(1390,1581.9)
  BOTTOM w12: U19.8@1287.99,1613.51 1358.39,1613.51 C83.2@1360,1611.9
  BOTTOM w20: R105.2@1035,1413.1 1046.9,1413.1 1080,1380 v1(1265,1380) ; 1355.18,742.76 T10.6@1375.7,742.76 ; 1355.18,837.24 T10.1@1375.7,837.24 ; C83.2@1360,1611.9 v1(1390,1581.9) ; 1375.7,708.24 T10.6@1375.7,742.76 ; 1375.7,777.28 T10.6@1375.7,742.76 ; 1375.7,802.72 T10.1@1375.7,837.24 ; 1375.7,871.76 T10.1@1375.7,837.24 ; 1413.1,708.24 T10.5@1413.1,742.76 1413.1,777.28 ; 1413.1,802.72 T10.2@1413.1,837.24 1413.1,871.76
AMP_VDD: C90.1 T8.1 T8.2 T8.5 T8.6 U20.8 | length 537.8
  BOTTOM w10: U20.8@1287.99,1418.51 1306.49,1418.51 C90.1@1360,1365
  BOTTOM w20: 1358.28,1087.76 T8.6@1378.8,1087.76 ; 1358.28,1182.24 T8.1@1378.8,1182.24 ; C90.1@1360,1365 1360,1240 1361,1239 ; 1378.8,1053.24 T8.6@1378.8,1087.76 ; 1378.8,1122.28 T8.6@1378.8,1087.76 ; 1378.8,1147.72 T8.1@1378.8,1182.24 ; 1378.8,1216.76 T8.1@1378.8,1182.24 ; 1416.2,1053.24 T8.5@1416.2,1087.76 1416.2,1122.28 ; 1416.2,1147.72 T8.2@1416.2,1182.24 1416.2,1216.76
ARD_5V: CN15.5 JP3.2 | length 725.9
  BOTTOM w40: JP3.2@2478.1,940 2468,929.9 2468,686 2653.1,500.9 CN15.5@2653.1,295
ARD_A0: CN16.1 U5.H5 | length 3034.4
  L3_SIG w3.5: 2730,1546 2757,1519 2771,1519 2793.53,1496.47 2813.11,1496.47 2835.27,1474.31 2843.76,1474.31 2853.7,1464.37 v4(2858.41,1464.37)
  L3_SIG w4: v1(1846,1140) 1886,1180 1886,1222 1798,1310 1798,1723 1850,1775 1880,1775 v1(1905,1800) ; v1(2694,1586) 2694,1582 2730,1546
  BOTTOM w5: v1(1846,1140) 1828,1122 1828,832.78 1829,831.78 1829,664 1856,637 2064,637 2175,526 2175,393 2153.1,371.1 CN16.1@2153.1,295 ; v1(1905,1800) 1910,1795 2005,1795 2027.5,1817.5 2403.72,1817.5 2653.22,1568 2683,1568 2694,1579 v1(2694,1586)
ARD_A1: CN16.2 U5.J3 | length 3260.1
  L2_GND w3.5: v3(2838.82,1504.09) 2838.73,1504.09 2838.73,1505 2848.66,1514.93 2848.66,1598.34 2845,1602 2845,1606.9
  L2_GND w5: 2845,1606.9 2845,1617.42 2852.62,1625.04 v5(2853.12,1625.04)
  L3_SIG w4: v1(1827,1192) 1827,1211 1733,1305 1733,1309 1665,1377 1665,1849 1851,2035 2045,2035 2065,2015 2340.12,2015 2410.12,1945 2541.24,1945 2601.24,1885 2637.04,1885 2839,1683.04 2839,1682.78 2847.78,1674 2851.13,1670.67 2851.13,1627.03 v5(2853.12,1625.04)
  BOTTOM w5: v1(1827,1192) 1827,1160 1813,1146 1813,658.23 1829.67,641.55 1856.22,615 1989,615 2053.1,550.9 CN16.2@2053.1,430
ARD_A2: CN16.3 U5.K1 | length 4057.3
  TOP w5: v1(2735,1894) 2735,1827 2747,1815 2759.49,1802.5 2825,1737 2825,1549.07 U5.K1@2819.04,1543.11
  L3_SIG w4: v1(1420,995) 1420,1220 1445,1245 1445,1380 1410,1415 1410,1640 1395,1655 1395,1835 1495,1935 1520,1935 1693,2108 2062,2108 2095,2075 2365.02,2075 2433.02,2007 2564.14,2007 2626.14,1945 2684,1945 v1(2735,1894)
  BOTTOM w5: v1(1420,995) 1390,995 1315,920 1315,690 1440,565 1440,510 1720,230 1795,230 1860,295 CN16.3@1953.1,295
ARD_A3: CN16.4 U5.H4 | length 2691.6
  L3_SIG w3.5: 2758,1570 2758,1569.59 2802.59,1525 2823.13,1525 2858.41,1489.72 2858.41,1484.08 v4(2858.45,1484.04)
  L3_SIG w4: v5(2727.11,1622.06) 2735,1614.17 2735,1593 2758,1570
  L5_GND w5: v7(2710,1620) 2711,1621 2724.8,1621 2725,1621.2 2726.25,1621.2 v5(2727.11,1622.06)
  BOTTOM w5: CN16.4@1853.1,430 1853.1,596.9 1798,652 1798,1153.66 1805,1160.66 1805,1195.5 1826.5,1217 1826.5,1795.75 1880.14,1849.39 2421.96,1849.39 2435,1836.35 2533.52,1836.35 2559.07,1810.8 2559.07,1704.58 2650.65,1613 2703,1613 v7(2710,1620)
ARD_A4: SB26.1 U5.N2 | length 2571.2
  TOP w5: v1(2687,1547.89) 2687,1547 2707.5,1526.5 2756.92,1526.5 U5.N2@2759.99,1523.43
  BOTTOM w5: SB26.1@1738.1,590 1738.1,633.1 1768,663 1768,1181.74 1811,1224.74 1811,1806 1905,1900 2400,1900 2448.61,1851.39 2541.61,1851.39 2576,1817 2576,1708.88 2654.89,1629.99 2687.21,1629.99 2692.22,1635 2703.78,1635 2716.21,1635.01 2730,1621.22 2730,1575 2702.89,1547.89 v1(2687,1547.89)
ARD_A5: SB28.1 U5.J2 | length 3095.8
  L2_GND w3.5: 2833,1601 2838.73,1595.27 v3(2838.73,1523.43)
  L2_GND w5: 2833,1601 2830,1604 2830,1631.12 2840,1641.12 2865.63,1641.12 v5(2866.13,1641.62)
  L3_SIG w4: v1(1495,1003) 1495,1010 1567,1082 1567,1882 1733,2048 2054.08,2048 2075.08,2027 2345.1,2027 2415.1,1957 2546.22,1957 2606.22,1897 2642.02,1897 2829.03,1709.99 2858.89,1709.99 2861.88,1710 2873,1698.88 2873,1648.49 v5(2866.13,1641.62)
  BOTTOM w5: v1(1495,1003) 1495,895 1560,830 1560,628.1 SB28.1@1598.1,590
ARD_D0: CN11.1 U5.H9 | length 2740.1
  L3_SIG w3.5: v4(2858.41,1385.63) 2858.41,1379.73 2848.66,1369.98 2848.66,1368.66 2848.48,1368.48 2848.48,1343.52 2912,1280 2919,1280
  L3_SIG w4: v1(1850,2003) 1870,2023 1896,2023 1982,1937 1982,1716 1859,1593 1859,1358 2167,1050 2593,1050 2628,1015 2752.08,1015 2852.1,1115.02 2852.1,1128.12 2912,1188.02 2912,1200.5 2925.9,1214.4 2925.9,1273.1 2919,1280
  BOTTOM w5: CN11.1@1653.1,2330 1653.1,2186.9 1835,2005 1848,2005 v1(1850,2003)
ARD_D1: CN11.2 U5.H10 | length 2515.4
  L3_SIG w3.5: v4(2858.41,1365.94) 2858.41,1344.2 2913.03,1289.58 2920.74,1289.58 2936.7,1273.62 2936.7,1270.3
  L3_SIG w4: v1(1885,2005) 1970,1920 1970,1723 1845,1598 1845,1355 2162,1038 2584,1038 2621,1001 2755.06,1001 2864.1,1110.04 2864.1,1123.14 2924,1183.04 2924,1194.98 2935.5,1206.48 2935.5,1213.48 2936.7,1214.68 2936.7,1270.3
  BOTTOM w5: CN11.2@1753.1,2195 1753.1,2136.9 v1(1885,2005)
ARD_D2: CN11.3 U5.G7 | length 1827.3
  L3_SIG w3.5: 2740,1570 2772,1538 2778.98,1538 2802.98,1514 2823.52,1514 2848.69,1488.83 2848.69,1479.99 2854.56,1474.12 2862.45,1474.12 2868.35,1468.22 2868.35,1440.65 2878.1,1430.9 v4(2878.1,1425)
  L3_SIG w4: v5(2688,1672) 2696,1664 2696,1629.98 2723,1602.98 2723,1587 2740,1570
  L5_GND w5: v7(2687,1690) 2688,1689 v5(2688,1672)
  BOTTOM w5: CN11.3@1853.1,2330 1853.1,2358.1 1900,2405 2420,2405 2433,2392 2433,2021.78 2487.78,1967 2526,1967 2687,1806 v7(2687,1690)
ARD_D3: CN11.4 U5.B12 | length 3267.4
  TOP w5: v1(1953.1,2264.1) 1953.1,2325 2005,2376.9 2005,2431 2020,2446 2020,2460 2065,2505 2565,2505 2640,2430 2725,2430 2770,2385 3210,2385 3300,2295 3300,2111.1 3370,2041.1 3370,1555 3390,1535 3390,1243.9 3330.6,1184.5 3144.5,1184.5 3083.44,1245.56 v3(3075.56,1245.56)
  L2_GND w3.5: v3(2978,1326.57) 2985.43,1326.57 3002,1310 3020,1310 3030,1300
  L2_GND w5: 3030,1300 3075,1255 3075,1246.12 v3(3075.56,1245.56)
  BOTTOM w5: CN11.4@1953.1,2195 v1(1953.1,2264.1)
ARD_D4: CN11.5 U5.C3 | length 2353.2
  L3_SIG w3.5: v4(2956.84,1503.74) 2956.84,1513.84 3013,1570
  L3_SIG w4: v1(2053.1,2260) 2119.1,2326 2440,2326 2476,2362 2606,2362 2781,2187 3256.02,2187 3368,2075.02 3368,1951 3252,1835 3150,1835 3106.52,1791.52 3106.52,1653.47 3028.05,1575 3018,1575 3013,1570
  BOTTOM w5: v1(2053.1,2260) CN11.5@2053.1,2330
ARD_D5: CN11.6 U5.D4 | length 2267
  L3_SIG w3.5: v4(2936,1484.84) 2938.5,1487.34 2938.5,1529.5 2979,1570
  L3_SIG w4: v1(2160,2280) 2194,2314 2446,2314 2482,2350 2598,2350 2773,2175 3251.04,2175 3356,2070.04 3356,1957 3249,1850 3143,1850 3065,1772 3065,1663 3032.98,1630.98 3004.1,1630.98 2989,1615.88 2989,1580 2979,1570
  BOTTOM w5: CN11.6@2153.1,2195 2153.1,2273.1 v1(2160,2280)
ARD_D6: CN11.7 U5.B9 | length 2099
  TOP w5: v1(2352,2273) 2374,2251 2589,2251 2594,2246 2726,2246 2892,2080 3130,2080 3185.6,2024.4 3185.6,1931.72 3265,1852.32 3265,1507.25 3270,1502.25 3270,1477.44 3248.7,1456.14 3248.7,1369.2 3215,1335.5 3215,1331 v1(3204.96,1320.96)
  L2_GND w3.5: v3(2976.53,1385.63) 3030,1385.63
  L2_GND w5: 3030,1385.63 3058.37,1385.63 3102,1342 v5(3102,1337)
  L3_SIG w3.5: v5(3102,1337) 3113.8,1325.2
  L3_SIG w4: 3113.8,1325.2 3118.04,1320.96 v1(3204.96,1320.96)
  BOTTOM w5: CN11.7@2253.1,2330 2323,2330 2352,2301 v1(2352,2273)
ARD_D7: CN11.8 U5.G11 | length 2642.5
  L2_GND w3.5: v3(2878.1,1346.26) 2888,1336.36 2888,1296.91 2888.04,1296.87 2888.04,1294.86 2898.2,1284.7 2898.2,1256.8 2909.1,1245.9 v5(2910.8,1245.9)
  L3_SIG w3.5: 2900,1208.5 2895,1213.5 2895,1230.1 v5(2910.8,1245.9)
  L3_SIG w4: v1(2348,1972) 2320,2000 2100,2000 1994,1894 1994,1709 1898,1613 1898,1513 1880,1495 1880,1357 2172,1065 2602,1065 2638,1029 2749,1029 2811,1091 2811,1131 2832,1152 2859,1152 2900,1193 2900,1208.5
  BOTTOM w5: v1(2348,1972) 2353.1,1977.1 CN11.8@2353.1,2195
ARD_D8: CN10.1 U5.C6 | length 1711
  TOP w5: v1(2513.1,2231) 2719.78,2231 2885.78,2065 3086.22,2065 3107,2044.22 3107,1978 3143,1942 3154.1,1942 3250,1846.1 3250,1497.5 v1(3252.5,1495)
  L3_SIG w3.5: v4(2956.84,1444.69) 2967.69,1444.69 2984,1461 3103,1461 3132,1490
  L3_SIG w4: 3132,1490 3133,1491 3199,1491 3213,1505 3242.5,1505 v1(3252.5,1495)
  BOTTOM w5: v1(2513.1,2231) CN10.1@2513.1,2330
ARD_D9: CN10.2 U5.C9 | length 1945.4
  TOP w5: v1(2613.1,2280) 2737,2280 2907,2110 3145,2110 3193.78,2061.22 3243.78,2061.22 3295,2010 3295,1519.69 3304,1510.69 3304,1469 3278.7,1443.7 3278.7,1329.92 3261.28,1312.5 v1(3235,1312.5)
  L2_GND w3.5: v3(2956.84,1385.63) 2966.59,1375.88 3025.12,1375.88
  L2_GND w5: 3025.12,1375.88 3027.85,1375.88 3037.73,1366 3059,1366 3080,1345 v5(3080,1340)
  L3_SIG w3.5: v5(3080,1340) 3080,1339 3093.8,1325.2
  L3_SIG w4: 3093.8,1325.2 3118,1301 3223.5,1301 v1(3235,1312.5)
  BOTTOM w5: CN10.2@2613.1,2195 v1(2613.1,2280)
ARD_D10: CN10.3 U5.A9 | length 1528.2
  TOP w5: v1(2713.1,2210) 2719.56,2210 2879.56,2050 3080,2050 3092,2038 3092,1971.78 3136.78,1927 3147.88,1927 3235,1839.88 3235,1463.66 3233.7,1462.36 3233.7,1389 3225.64,1380.94 3024.06,1380.94 3019.37,1385.63 U5.A9@2996.21,1385.63
  BOTTOM w5: v1(2713.1,2210) CN10.3@2713.1,2330
ARD_D11: CN10.4 U5.B5 | length 1938.7
  L2_GND w3.5: v3(2976.53,1464.37) 2993.37,1464.37 3002.25,1473.25 3050.25,1473.25 3064,1487 3064,1517 v5(3059,1522)
  L3_SIG w3.5: v5(3059,1522) 3059,1538.03 3070.27,1549.3
  L3_SIG w4: v1(2813.1,2261.9) 2827,2248 2928,2248 3047,2367 3406,2367 3490,2283 3490,1915 3220,1645 3165.97,1645 3070.27,1549.3
  BOTTOM w5: CN10.4@2813.1,2195 v1(2813.1,2261.9)
ARD_D12: CN10.5 U5.A5 | length 1923.2
  TOP w5: U5.A5@2996.21,1464.37 3031.37,1464.37 3052,1485 3127,1485 3132,1490 3185,1490 3190,1495 3190,1541 v1(3173,1558)
  L3_SIG w4: v1(2913.1,2265) 2913.1,2265.1 3030,2382 3412,2382 3505,2289 3505,1910 3225,1630 3185,1630 3160,1605 3160,1571 v1(3173,1558)
  BOTTOM w5: v1(2913.1,2265) CN10.5@2913.1,2330
ARD_D13: CN10.6 SB1.2 U5.K4 | length 2401.3
  TOP w5: SB1.2@1840,2375 v1(1915,2375)
  L2_GND w3.5: 2736.67,1570 2736.67,1563.33 2766,1534 2766,1523 2775.32,1513.68 2783.71,1513.68 2789.61,1507.78 2789.61,1499 2794.61,1494 2809.1,1494 v3(2819.04,1484.06)
  L2_GND w5: 2736.67,1570 2736.67,1592.27 2734.5,1594.44 2734.5,1607.5 2756.5,1629.5 2756.5,1631.43 2763.98,1638.91 v5(2763.98,1645)
  L3_SIG w4: v1(1915,2375) 2000,2375 2037,2338 2376,2338 2424,2386 2669,2386 2689,2366 2689,2318.98 2796.98,2211 2963.03,2211 v1(3015,2262.97)
  L5_GND w5: v5(2763.98,1645) v7(2777,1658)
  BOTTOM w5: v7(2777,1658) 2794.26,1675.26 2794.26,1809.99 2710,1894.25 2710,1961 2854,2105 2950,2105 3013.1,2168.1 CN10.6@3013.1,2195 3013.1,2261.07 v1(3015,2262.97)
ARD_D14: CN2.10 CN10.9 SB25.1 U5.D5 | length 6328.4
  TOP w5: v1(1510,2245) 1510,2215 1725,2000 1725,1300 1787,1238 v1(1787,1172)
  L3_SIG w3.5: v4(2937.16,1464.37) 2940.76,1464.37 2949.39,1473 2960,1473 2986,1499 2996,1499 3021.25,1524.25 3021.25,1526.29 3034.48,1539.52 3043.51,1539.52 3053.29,1549.3
  L3_SIG w4: v1(1510,2245) 1510,2310 1616,2416 2682,2416 2719,2379 2719,2325 2808,2236 2935,2236 3049,2350 3390,2350 v1(3410,2330) 3435,2305 3435,2185 3465,2155 3465,1910 3213,1658 3161.99,1658 3053.29,1549.3
  BOTTOM w5: v1(1787,1172) 1783,1168 1783,656.78 1781,654.78 1781,607.1 SB25.1@1798.1,590 ; CN10.9@3313.1,2330 v1(3410,2330) 3557,2330 3577,2310 3910,2310 3930,2330 3930,2385 3955,2410 4130,2410 4170,2370 4170,2320 4180,2310 4330.85,2310 CN2.10@4367.43,2273.42
ARD_D15: CN2.7 CN10.10 SB27.1 U5.C4 | length 5491.1
  L3_SIG w3.5: v4(2956.84,1484.06) 2982.78,1510 2994,1510 3010,1526 3010,1530 3030,1550
  L3_SIG w4: v1(2367,2355) 2412,2400 2676,2400 2704,2372 2704,2323 2803,2224 2944,2224 3055,2335 3375,2335 3413.1,2296.9 v1(3413.1,2269.9) 3413.1,2181.9 3450,2145 3450,1915 3210,1675 3162.01,1675 3038.01,1551 3031,1551 3030,1550
  BOTTOM w5: SB27.1@1658.1,590 1753,684.9 1753,1195.74 1795,1237.74 1795,1814 1897,1916 2348,1916 2374,1942 2374,2107 2395,2128 2395,2250 2381,2264 2381,2341 v1(2367,2355) ; CN10.10@3413.1,2195 v1(3413.1,2269.9) 3428.2,2285 3530,2285 3592,2223 4080.79,2223 CN2.7@4131.21,2273.42
AUDIO_RST: R83.2 U5.F11 U18.25 | length 4546.2
  TOP w5: v1(1240,795) 1240,840 1195,885 974,885 885,974 885,1195 934,1244 1048,1244 1089,1285 1089,1664 1373,1948 1373,2203 1359,2217 1252,2217 v1(1245,2210)
  L3_SIG w3.5: v4(2898.23,1345.44) 2898.23,1345.77 2928.5,1315.5 2966.15,1315.5 2993.02,1288.63 2993.02,1275
  L3_SIG w4: v1(1240,795) 1253,808 1791.96,808 1898.96,915 2041,915 2058,898 2174,898 2262,810 2591,810 2711.5,930.5 2806.5,930.5 2995.5,1119.5 2995.5,1193.54 3010,1208.04 3010,1258.02 2993.02,1275
  BOTTOM w5: U18.25@1160.28,2078.9 1175.8,2078.9 1195.9,2099 1195.9,2165.9 R83.2@1210,2180 1240,2210 v1(1245,2210)
BLGND: C47.2 C48.2 C55.2 C56.2 C57.2 C58.2 C59.2 L4.2 R67.2 R73.2 R76.2 U15.3 U15.9 | length 641.2
  TOP w15: U15.3@2151.17,306.8 2184.9,306.8 2190.99,312.89 v2(2193.67,312.89)
  TOP w20: v1(1870,230) 1870,215 R76.2@1895,190 ; 2041.98,475 C48.2@2073,475 ; 2055,520.98 C47.2@2055,545 ; 2055,569.02 C47.2@2055,545 ; 2073,436.98 C48.2@2073,475 ; 2073,513.02 C48.2@2073,475 ; 2080.52,545 C47.2@2055,545 ; 2104.02,475 C48.2@2073,475 ; v1(2155,455) L4.2@2195,455 ; v2(2248.1,67) C56.2@2248.1,107 ; R73.2@2288.1,290 2313.1,290 v2(2323.1,300) ; R67.2@2288.1,345 v2(2323.1,345) ; v2(2323.1,55) C57.2@2323.1,100 ; v2(2373.1,55) C58.2@2373.1,100 ; v2(2423.1,55) C59.2@2423.1,100 ; v2(2493.1,70) C55.2@2493.1,115
  other v1: 2073.1,265 2113.1,265 2093.1,295 2073.1,320 2113.1,320 2095,525 2120,525 2095,550 2120,550
BOOT0: R20.2 R21.2 U5.E5 | length 381.3
  TOP w5: R20.2@3055,1650 3056,1650 v1(3086,1680) 3115,1651 R21.2@3115,1650
  L3_SIG w3.5: v4(2917.47,1464.37) 2927.41,1474.31 2939.26,1474.31 2947,1482.05 2947,1521 2996,1570
  L3_SIG w4: 2996,1570 3016,1590 3022,1590 3086,1654 v1(3086,1680)
CAL: R94.1 T6.3 U21.3 | length 1260.3
  TOP w5: v1(980,1100) 1000,1120 1116.22,1120 1161.22,1075 1215,1075 1330,1190 1350,1190 1705,1545 v1(1705,1645)
  BOTTOM w5: U21.3@898.74,1081.1 961.1,1081.1 v1(980,1100) ; T6.3@1700.5,1522.24 1700.5,1605.5 R94.1@1705,1610 v1(1705,1645)
CAL_D: R95.2 T6.1 T6.2 T6.5 T6.6 T7.4 T9.4 U19.3 | length 2070.9
  TOP w20: v1(1190,1640) 1580,1640 v1(1615,1675) ; v1(1700.5,701.26) v1(1700.5,1034.5)
  L3_SIG w20: v1(1615,1675) 1615,1220 1700.5,1134.5 v1(1700.5,1034.5)
  BOTTOM w12: U19.3@1112.01,1664.7 1150.3,1664.7 1175,1640 v1(1190,1640)
  BOTTOM w20: 1605.18,1427.76 T6.6@1625.7,1427.76 ; 1605.18,1522.24 T6.1@1625.7,1522.24 ; 1606.98,1610 R95.2@1635,1610 ; 1625.7,1393.24 T6.6@1625.7,1427.76 ; 1625.7,1462.28 T6.6@1625.7,1427.76 ; 1625.7,1487.72 T6.1@1625.7,1522.24 ; 1625.7,1556.76 T6.1@1625.7,1522.24 ; 1635,1576.98 R95.2@1635,1610 ; 1635,1643.02 R95.2@1635,1610 ; 1663.02,1610 R95.2@1635,1610 ; 1663.1,1393.24 T6.5@1663.1,1427.76 1663.1,1462.28 ; 1663.1,1487.72 T6.2@1663.1,1522.24 1663.1,1556.76 ; v1(1700.5,701.26) T9.4@1700.5,742.76 ; v1(1700.5,1034.5) T7.4@1700.5,1087.76
CAMERA_CLK: CN1.21 R100.1 | length 1799.6
  TOP w5: CN1.21@2209.4,2400 2209.4,2199.6 v1(2210,2199) ; v1(2564,2182) 2688,2182 2835,2035 2935,2035 3058,1912 3141.66,1912 3220,1833.66 3220,1469.72 v1(3216.28,1466)
  L3_SIG w4: v1(2210,2199) 2547,2199 v1(2564,2182)
  BOTTOM w5: R100.1@3165,1495 3195,1495 3216.28,1473.72 v1(3216.28,1466)
CKOUT: CN2.18 CN2.20 U1.3 U2.3 U5.J4 U16.4 U17.4 | length 5907.6
  TOP w5: v1(370,2490) 385,2475 410,2475 438.27,2503.27 U1.3@446.53,2503.27 ; v1(1202,2478) 1237,2478 1262.27,2503.27 U2.3@1273.22,2503.27
  L3_SIG w3.5: 2730,1563 2764,1529 2774,1529 2799.03,1503.97 2819.76,1503.97 2838.91,1484.82 v4@2838.91,1484.48
  L3_SIG w4: v1(408.66,2411.34) 370,2450 v1(370,2490) 547,2490 577,2520 846,2520 888,2478 v1(1202,2478) 1202,2444.34 v1(1235,2411.34) 1361.34,2411.34 1440,2490 1580.01,2490 1613.01,2523 2518,2523 v1(2530,2535) ; v5(2681,1631) 2681,1628 2711,1598 2711,1582 2730,1563 ; CN2.18@4209.95,2352.16 4252.79,2395 4324.59,2395 CN2.20@4367.43,2352.16
  L5_GND w5: v5(2681,1631) v7(2681,1645)
  BOTTOM w5: v1(408.66,2411.34) U17.4@440.13,2411.34 ; v1(1235,2411.34) U16.4@1266.82,2411.34 ; v7(2681,1645) 2705,1669 2705,1820 2538.61,1986.39 2489.61,1986.39 2448,2028 2448,2493 2490,2535 v1(2530,2535) 2555,2535 2635,2455 4107.11,2455 CN2.18@4209.95,2352.16
  other v4: 2838.94,1484.45
CTP_INT: CN13.2 R89.1 U5.G6 | length 4239.9
  L3_SIG w3.5: v4(2878.1,1444.69) 2888.03,1454.62 2901.83,1454.62 2907.72,1460.51 2907.72,1488.1 2920,1500.38 2920,1539
  L3_SIG w4: v1(650,1821) 706,1765 825,1765 936,1654 1076,1654 1168,1746 1168,2022 1286,2140 1325,2140 1353,2168 1494.04,2168 1565.04,2239 2064,2239 2075,2250 2460,2250 2480,2270 2575.96,2270 2669.96,2176 2733,2176 2760,2149 3241,2149 3332,2058 3332,1973 3234,1875 3127,1875 3007.11,1755.11 3007.11,1692.89 2991,1676.78 2991,1651.84 2965,1625.84 2965,1591 2959,1585 2959,1578 2920,1539
  BOTTOM w5: CN13.2@572.63,1768.59 572.63,1790.63 R89.1@603,1821 v1(650,1821)
D0: CN6.18 U4.B6 U5.K10 | length 2162.9
  TOP w4: U4.B6@2206.92,1623.82 2214.18,1616.56 v6(2225.56,1616.56)
  TOP w5: v1(1986,797.9) CN6.18@2044.44,797.9
  L3_SIG w3.5: 2803.98,1443 2805.43,1441.55 2825.59,1441.55 2832.2,1434.94 2862.26,1434.94 2868.16,1429.04 2868.16,1420.16 2863.06,1415.06 2854.37,1415.06 2848.66,1409.35 2848.66,1401.45 2842.59,1395.38 2834.69,1395.38 2828.75,1389.44 2828.75,1380.36 2819.04,1370.65 v4(2819.04,1365.96)
  L3_SIG w4: v6(2225.56,1616.56) 2224,1615 2224,1569 2229,1564 2258,1564 2267,1555 2267,1524 2283,1508 2283,1452.78 2293.78,1442 2331,1442 2362,1473 2535,1473 2539,1469 2539,1448 2545,1442 2759,1442 2760,1443 2803.98,1443
  BOTTOM w4: 2005,1613.44 2029.56,1638 2204.12,1638 v6(2225.56,1616.56)
  BOTTOM w5: v1(1986,797.9) 1962.66,797.9 1931,829.56 1931,881.22 1897.5,914.72 1897.5,1466.5 1930,1499 1930,1538.44 2005,1613.44
D1: CN6.17 U4.C5 U5.H11 | length 2013.9
  TOP w4: U4.C5@2177.39,1594.29 v6(2192,1608.9)
  TOP w5: CN6.17@1930.26,809.71 1946.34,809.71 v1(1960.97,824.34)
  L2_GND w3.5: v5(2753,1392) 2756.38,1395.38 2803.39,1395.38 2803.72,1395.05 2834.36,1395.05 2834.69,1395.38 2842.77,1395.38 2848.66,1389.49 2848.66,1356.01 v3(2858.41,1346.26)
  L3_SIG w3.5: 2654,1367 2728,1367 v5(2753,1392)
  L3_SIG w4: v6(2192,1608.9) 2211,1589.9 2211,1548 2219,1540 2219,1474.88 2229,1464.88 2229,1440 2214,1425 2214,1415.94 2272.94,1357 2468.98,1357 2479.98,1368 2515,1368 2538,1345 2632,1345 2654,1367
  BOTTOM w4: 2111,1390 2111,1392 2089,1414 2089,1440 2076,1453 2076,1486 2091,1501 2091,1518 2135,1562 2135,1603 2155,1623 2177.9,1623 v6(2192,1608.9)
  BOTTOM w5: v1(1960.97,824.34) 1954,831.31 1954,856 1971.88,873.88 1992.29,873.88 2041.39,922.98 2091.54,922.98 2111,942.44 2111,1390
